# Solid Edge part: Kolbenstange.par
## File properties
Username: bmolnar
Dokumentum tartalom típus: 0
Author: bmolnar
Last saved by: bmolnar
Revision: 86
Sűrűség: 0,000 kg/m^3
Pontosság: 0,990
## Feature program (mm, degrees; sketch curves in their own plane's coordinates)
base feature "unnamed BaseFeature 1"
sketch for "unnamed Protrusion 1" plane through (22, 0.0012, 0) normal (1, 0, 0) x-axis (0, 1, 0)
  circle centre (-0.0012, 0) radius 8
extrude "unnamed Protrusion 1" add finite 9.1 along -normal
sketch for "Furat_1" plane through (-8, 0, 0.0012) normal (-1, 0, 0) x-axis (0, -1, 0)
  hole centre (0, -0.0012) bore radius 1.621
hole "Furat_1" nominal diameter 4 finite  VBottomAngle = 118 deg; ThreadDepth = 9 mm
chamfer "Letörés_1" setback 0.3  SetBackValue2 = 45 deg
sketch for "Kihúzás_2" plane through (22, 0.0012, 0) normal (1, 0, 0) x-axis (0, 1, 0)
  circle centre (-0.0012, 0) radius 8
extrude "Kihúzás_2" add finite 16.1 along +normal
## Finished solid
Body 1: solid body, 18 faces, 24 edges, 8 vertices.
  Faces by surface: plane 8, cylinder 5, cone 3, torus 2
  Edges by curve: circle 14, line 6, curve on surface 2, ellipse 2
Bounding box of the edges (mm; curved faces can reach further): 48.100 x 16.000 x 16.000, from (-10, -8, -8) to (38.1, 8, 8).
Cylindrical faces by radius (mm): R1.621 x2, R2.125 x1, R4 x1, R8 x1
Conical faces (half-angle, radius in mm at the cone's reference point): 45 deg R1.921 x1, 45 deg R2.225 x1, 59 deg R1.621 x1
Toroidal faces (ring radius, tube radius in mm): R1.925 r0.2 x1, R2.7 r1.3 x1
Planar faces by outward normal: +x 1, +z 1, -x 3, -z 1, oblique 2
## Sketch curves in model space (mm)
circle centre (22, 0, 0) radius 8
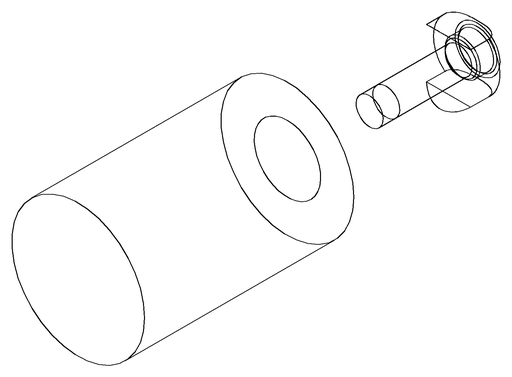
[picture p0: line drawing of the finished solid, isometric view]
